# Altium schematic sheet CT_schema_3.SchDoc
size 533 x 490 mm
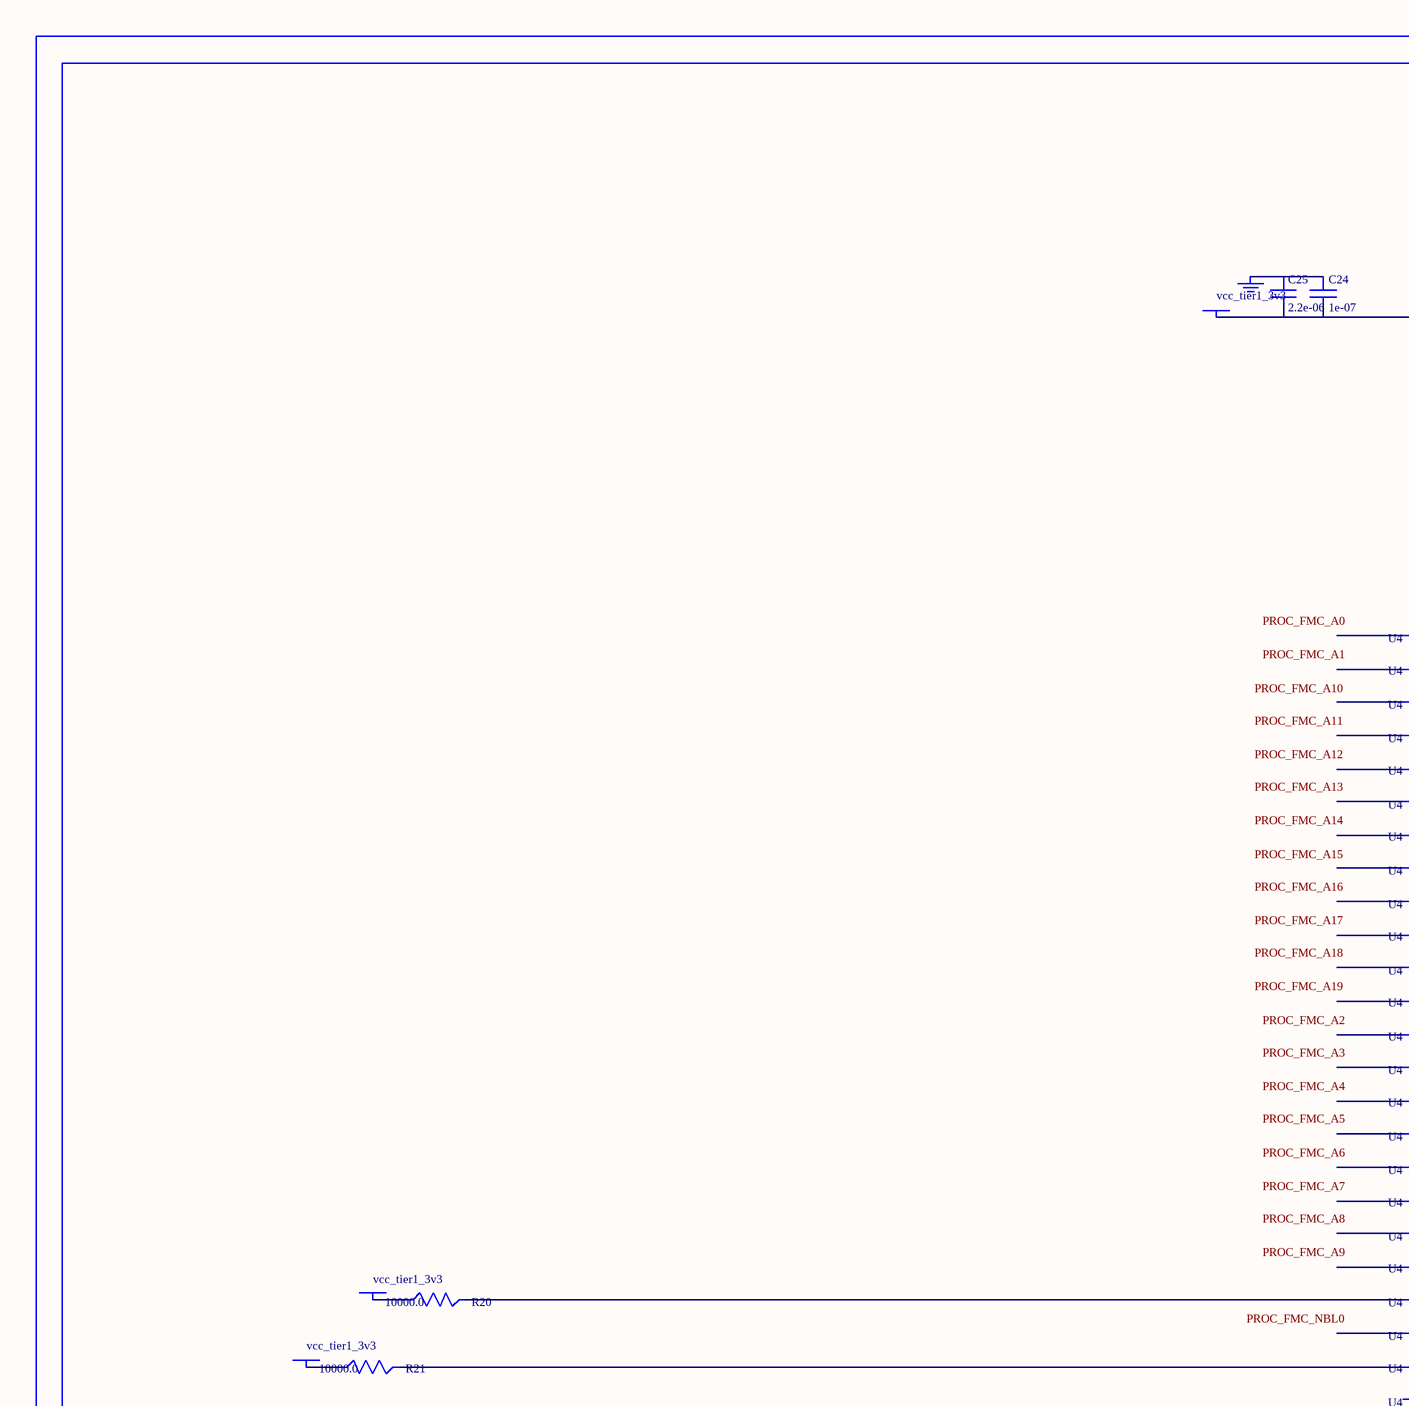
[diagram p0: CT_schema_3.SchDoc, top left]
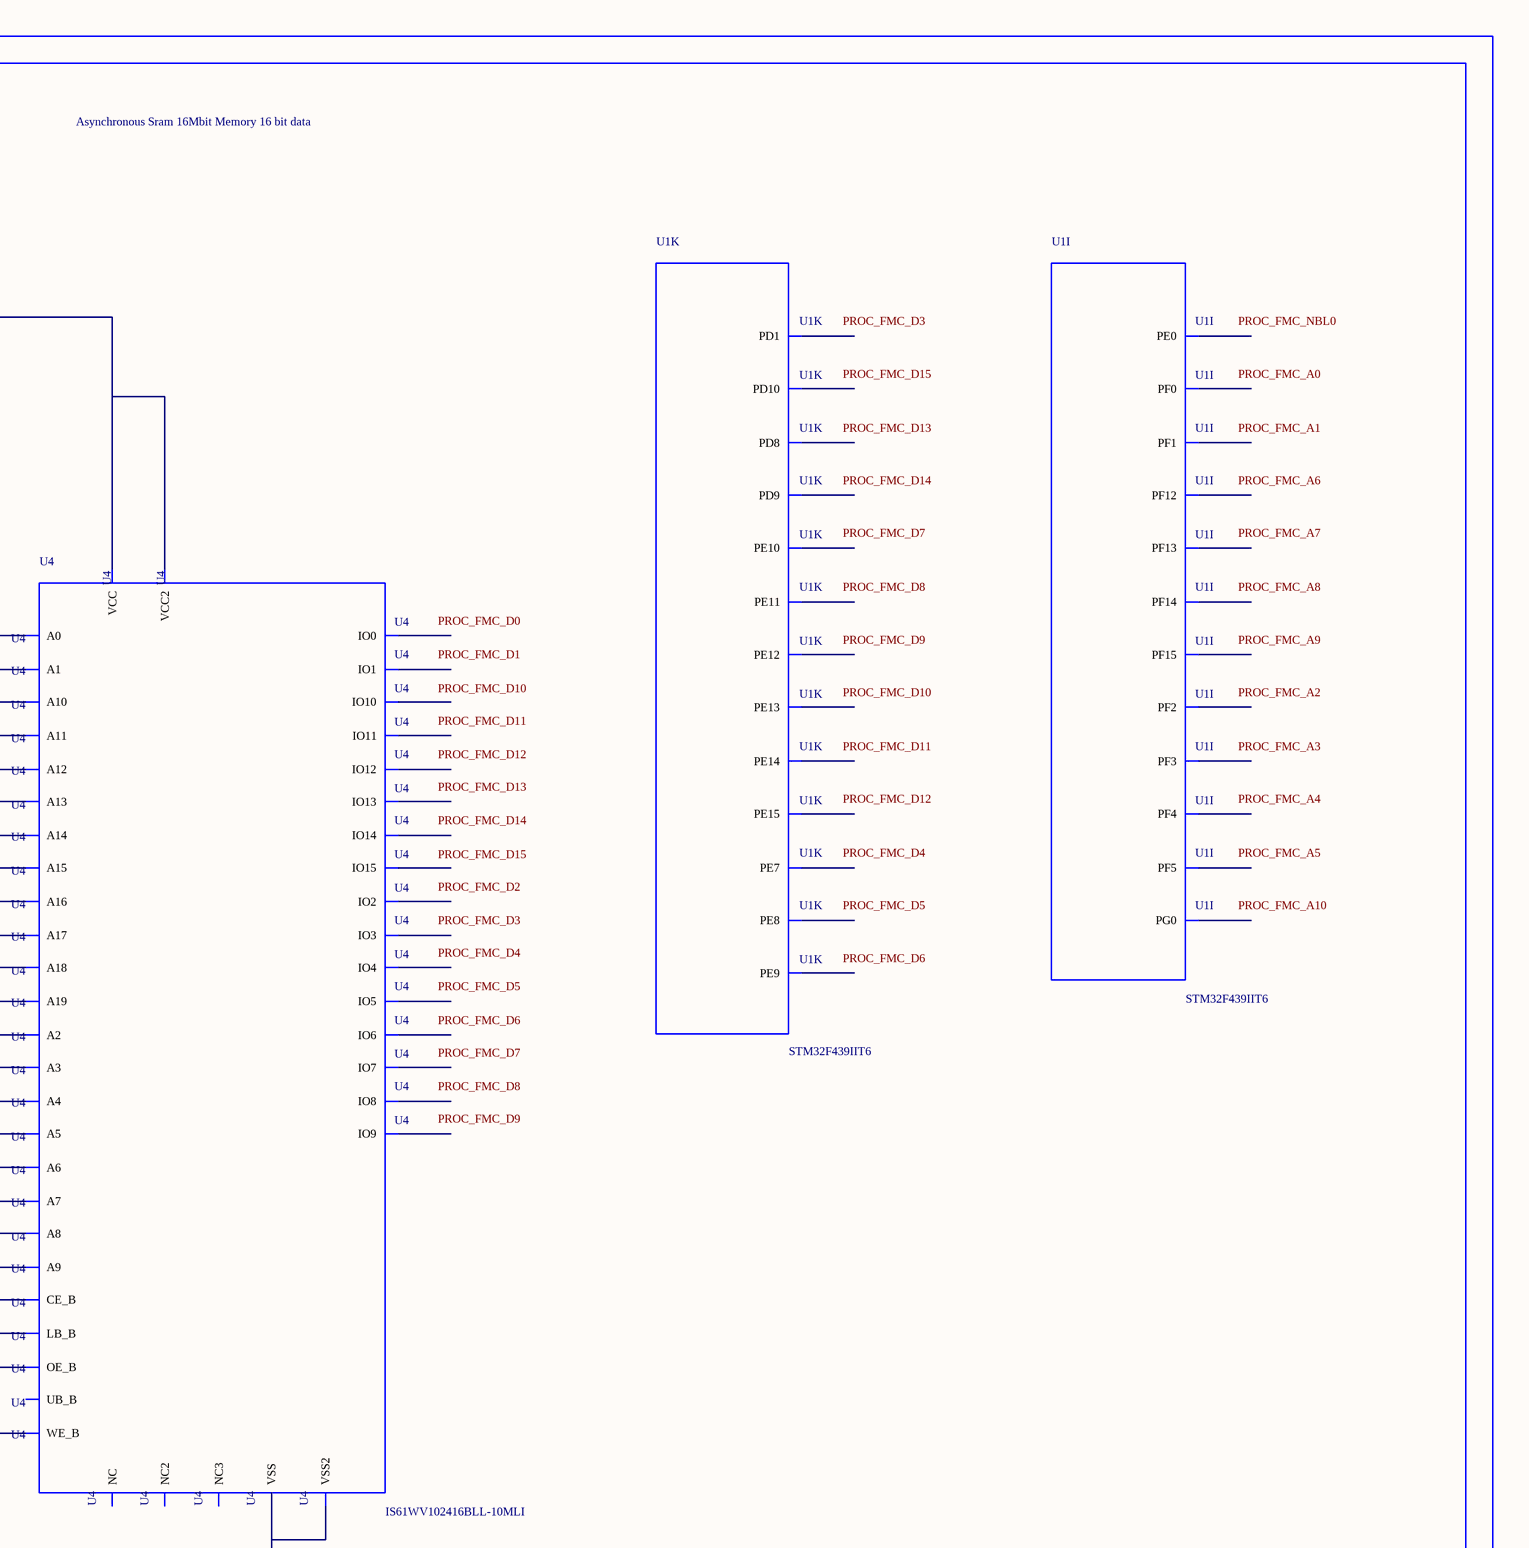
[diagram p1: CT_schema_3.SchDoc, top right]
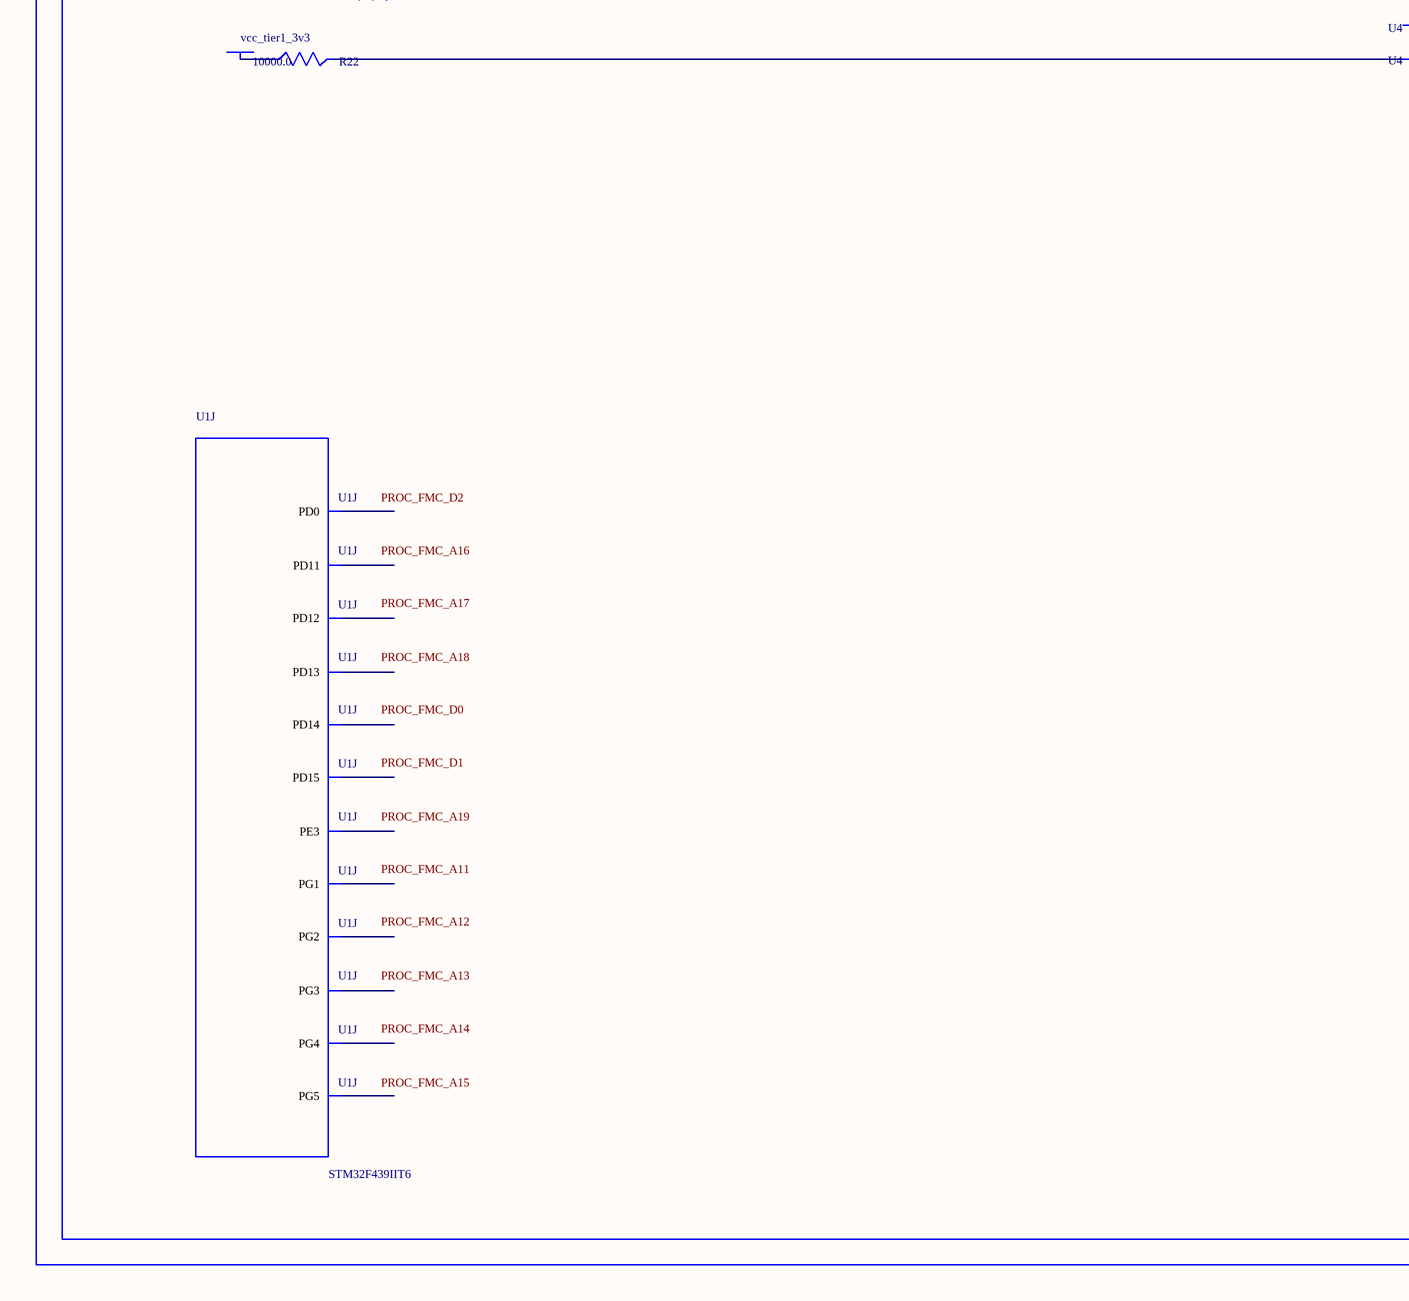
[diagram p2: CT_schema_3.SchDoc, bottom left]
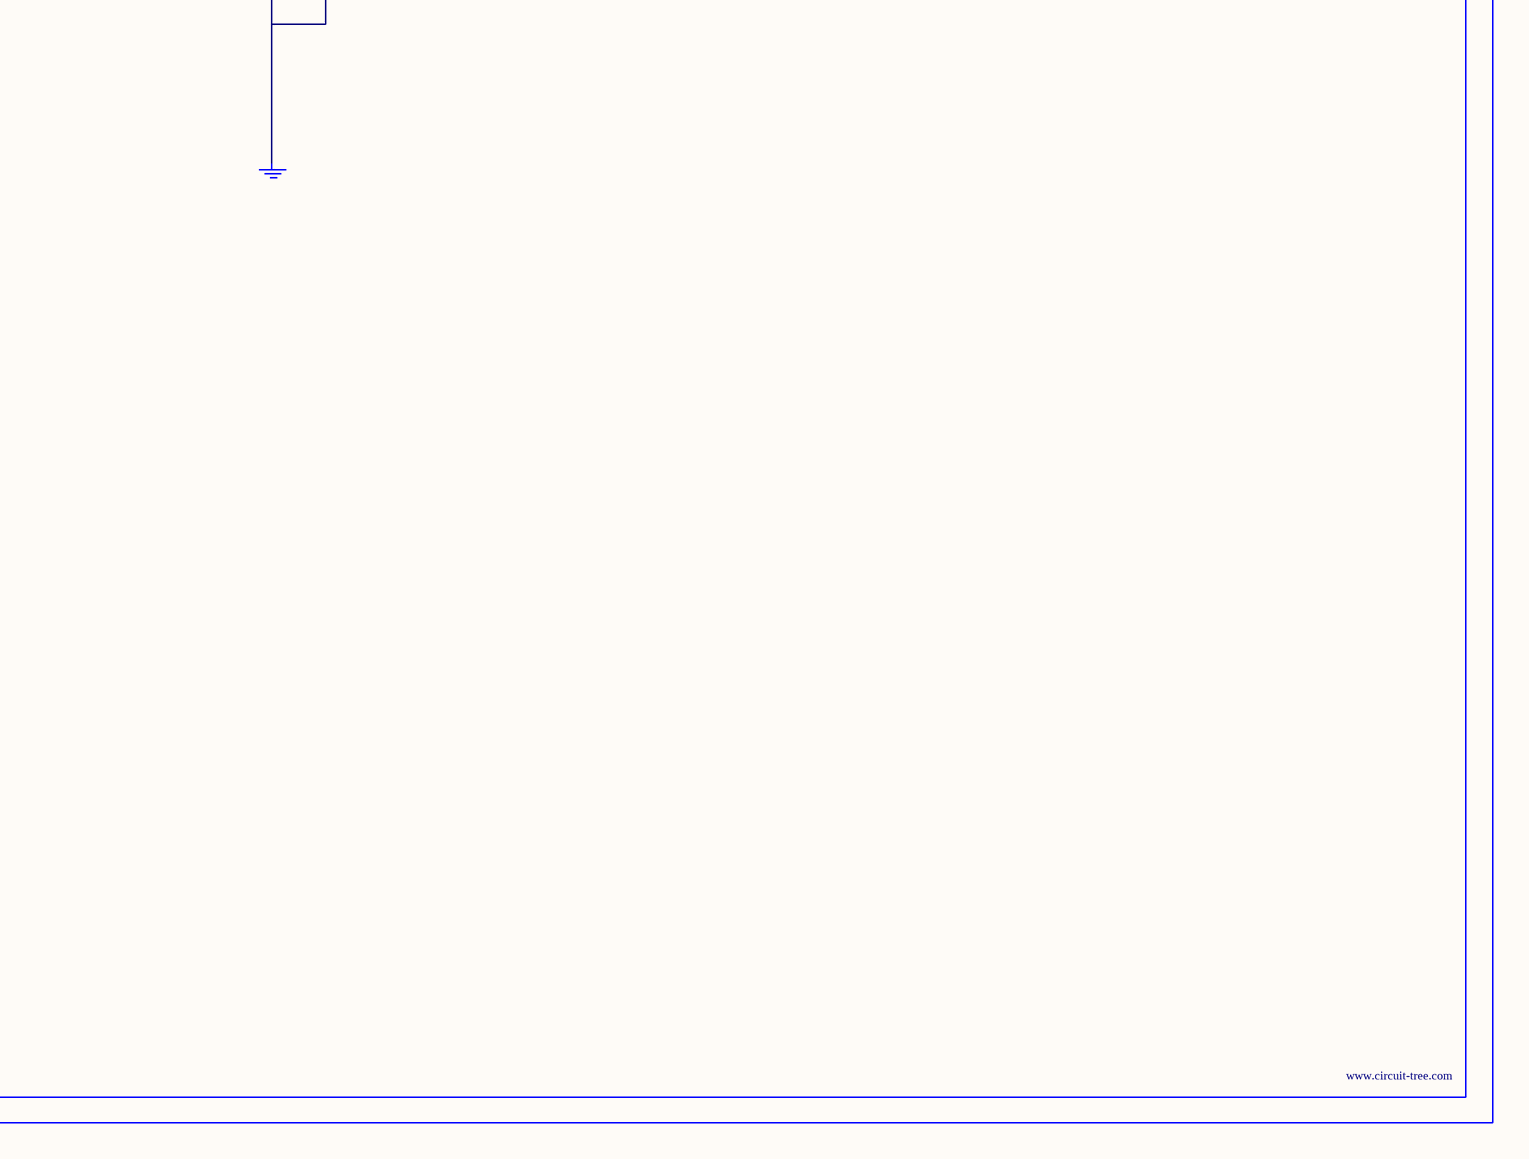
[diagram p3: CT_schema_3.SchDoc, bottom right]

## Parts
BORDER2  (no value)
C24  1e-07  [C0402]
C25  2.2e-06  [C0603]
GND_INSTANCE_2_0  (no value)
GND_INSTANCE_2_1  (no value)
POWER_INSTANCE_2_0  vcc_tier1_3v3
POWER_INSTANCE_2_1  vcc_tier1_3v3
POWER_INSTANCE_2_2  vcc_tier1_3v3
POWER_INSTANCE_2_3  vcc_tier1_3v3
R20  10000.0  [R0603]
R21  10000.0  [R0603]
R22  10000.0  [R0603]
U1  STM32F439IIT6  [LQFP176]  (parts I,J,K of 11)
U4  IS61WV102416BLL-10MLI  [IS61WV102416BLL-10MLI]

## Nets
NetC24_1: C24.1 C25.1 GND_INSTANCE_2_0.0(GND)
NetC24_2: C24.2 C25.2 POWER_INSTANCE_2_0.0(PWR) U4.D6(VCC) U4.E1(VCC2)
NetGND_INSTANCE_2_1_0: GND_INSTANCE_2_1.0(GND) U4.D1(VSS) U4.E6(VSS2)
NetPOWER_INSTANCE_2_1_0: POWER_INSTANCE_2_1.0(PWR) R20.1
NetPOWER_INSTANCE_2_2_0: POWER_INSTANCE_2_2.0(PWR) R21.1
NetPOWER_INSTANCE_2_3_0: POWER_INSTANCE_2_3.0(PWR) R22.1
NetR20_2: R20.2 U4.B5(CE_B)
NetR21_2: R21.2 U4.A2(OE_B)
NetR22_2: R22.2 U4.G5(WE_B)

Not connected (* = marked no-connect by the designer): U1 2(PE3) 16(PF0) 17(PF1) 18(PF2) 19(PF3) 20(PF4) 21(PF5) 60(PF12) 63(PF13) 64(PF14) 65(PF15) 66(PG0) 67(PG1) 68(PE7) 69(PE8) 70(PE9) 73(PE10) 74(PE11) 75(PE12) 76(PE13) 77(PE14) 78(PE15) 96(PD8) 97(PD9) 98(PD10) 99(PD11) 100(PD12) 101(PD13) 104(PD14) 105(PD15) 106(PG2) 107(PG3) 108(PG4) 109(PG5) 142(PD0) 143(PD1) 169(PE0); U4 A1(LB_B) A3(A0) A4(A1) A5(A2) A6(NC) B1(IO8) B2(UB_B) B3(A3) B4(A4) B6(IO0) C1(IO9) C2(IO10) C3(A5) C4(A6) C5(IO1) C6(IO2) D2(IO11) D3(A17) D4(A7) D5(IO3) E2(IO12) E3(NC2) E4(A16) E5(IO4) F1(IO14) F2(IO13) F3(A14) F4(A15) F5(IO5) F6(IO6) G1(IO15) G2(A19) G3(A12) G4(A13) G6(IO7) H1(A18) H2(A8) H3(A9) H4(A10) H5(A11) H6(NC3)

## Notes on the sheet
- Labels drawn without touching a wire or pin: PROC_FMC_A0, PROC_FMC_A1, PROC_FMC_A2, PROC_FMC_A3, PROC_FMC_A4, PROC_FMC_A5, PROC_FMC_A6, PROC_FMC_A7, PROC_FMC_A8, PROC_FMC_A9, PROC_FMC_A10, PROC_FMC_A11, PROC_FMC_A12, PROC_FMC_A13, PROC_FMC_A14, PROC_FMC_A15, PROC_FMC_A16, PROC_FMC_A17, PROC_FMC_A18, PROC_FMC_A19, PROC_FMC_D0, PROC_FMC_D1, PROC_FMC_D2, PROC_FMC_D3, PROC_FMC_D4, PROC_FMC_D5, PROC_FMC_D6, PROC_FMC_D7, PROC_FMC_D8, PROC_FMC_D9, PROC_FMC_D10, PROC_FMC_D11, PROC_FMC_D12, PROC_FMC_D13, PROC_FMC_D14, PROC_FMC_D15, PROC_FMC_NBL0

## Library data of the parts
BORDER2 = BORDER_PAGE2
C24 = C0402C104K3RACTU
C25 = C0603C225K8RACTU
GND_INSTANCE_2_0 GND_INSTANCE_2_1 = GND
POWER_INSTANCE_2_0-POWER_INSTANCE_2_3 = PWR
R20-R22 = RC0603JR-0710KL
